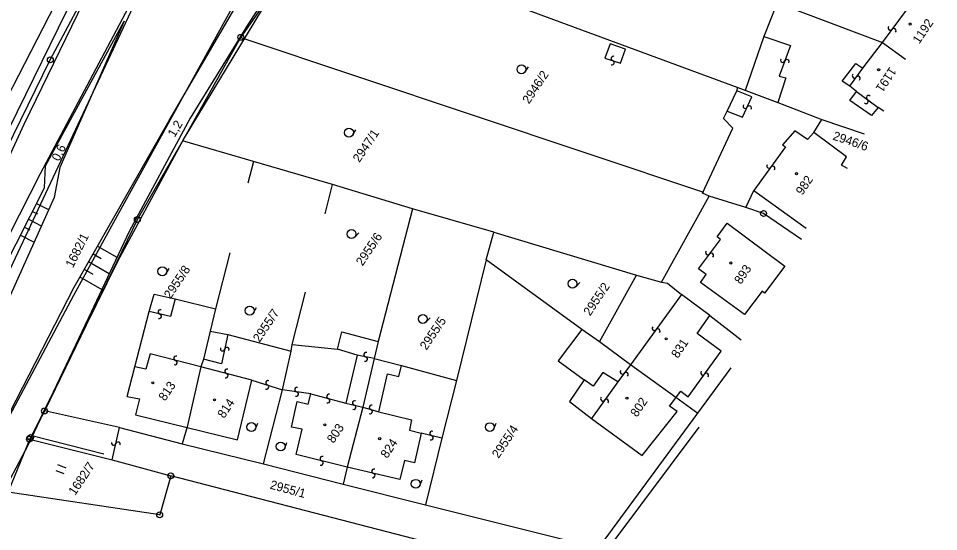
# Model space of a CAD drawing. Extents: x -658910 to -658078, y -1170373 to -1169331.
# Drawn here: x -658303.7 to -658147.9, y -1169709.4 to -1169622.6 of the extents above; entities that cross this region are included whole.
import ezdxf

# ---------------------------------------------------------------- set-up
doc = ezdxf.new("R2010")
doc.units = 0
for name, color, linetype in [('Vrstva 1', 7, 'Continuous'), ('Vrstva 10', 7, 'Continuous'), ('Vrstva 11', 7, 'Continuous'), ('Vrstva 12', 7, 'Continuous'), ('Vrstva 8', 7, 'Continuous'), ('Vrstva 9', 7, 'Continuous')]:
    doc.layers.add(name, color=color, linetype=linetype)

msp = doc.modelspace()

# ---------------------------------------------------------------- linework, layer by layer
at = {"layer": 'Vrstva 1'}
for p, q in [((-658253.461, -1169607.728), (-658266.16, -1169625.929)), ((-658266.16, -1169625.929), (-658275.871, -1169643.228)), ((-658266.1, -1169625.8), (-658266, -1169625.8)), ((-658298.339, -1169629.6), (-658298.239, -1169629.6)), ((-658275.871, -1169643.228), (-658283.521, -1169656.539)), ((-658283.521, -1169656.539), (-658299.242, -1169688.919)), ((-658283.61, -1169656.6), (-658283.51, -1169656.6)), ((-658299.242, -1169688.919), (-658301.781, -1169693.669)), ((-658299.331, -1169688.98), (-658299.231, -1169688.98)), ((-658301.87, -1169693.73), (-658301.77, -1169693.73)), ((-658301.82, -1169693.73), (-658287.82, -1169697.23)), ((-658301.672, -1169693.458), (-658301.572, -1169693.458)), ((-658301.672, -1169693.458), (-658301.572, -1169693.458)), ((-658287.82, -1169697.23), (-658277.891, -1169699.949)), ((-658277.891, -1169699.949), (-658279.77, -1169706.539)), ((-658277.941, -1169699.949), (-658277.841, -1169699.949)), ((-658279.77, -1169706.539), (-658305.441, -1169702.699)), ((-658279.82, -1169706.539), (-658279.72, -1169706.539))]:
    msp.add_line(p, q, dxfattribs=at)
msp.add_lwpolyline([(-658387.09, -1169803.74), (-658379.66, -1169787.031), (-658371.41, -1169770.08), (-658363.031, -1169753.09), (-658350.949, -1169718.6), (-658329.91, -1169685.09), (-658309.48, -1169652.309), (-658298.289, -1169629.6), (-658291.762, -1169617.34), (-658282.25, -1169598.42), (-658273.73, -1169581.691), (-658253.98, -1169552.23), (-658232.398, -1169524.699), (-658206.289, -1169500.25)], dxfattribs=at)
for centre in [(-658266.05, -1169625.8), (-658298.289, -1169629.6), (-658283.56, -1169656.6), (-658299.281, -1169688.98), (-658301.82, -1169693.73), (-658301.622, -1169693.458), (-658301.622, -1169693.458), (-658277.891, -1169699.949), (-658279.77, -1169706.539)]:
    msp.add_circle(centre, 0.499, dxfattribs=at)
at = {"layer": 'Vrstva 10'}
for points in [[(-658276.584, -1169590.485), (-658283.44, -1169602.541), (-658287.975, -1169611.492), (-658289.687, -1169613.574), (-658302.78, -1169640.536), (-658308.513, -1169652.938), (-658311.735, -1169652.624), (-658329.784, -1169644.735), (-658339.953, -1169641.872), (-658339.466, -1169639.877), (-658334.347, -1169641.667), (-658319.785, -1169646.697), (-658309.854, -1169650.681), (-658305.208, -1169641.097), (-658290.001, -1169610.092), (-658286.058, -1169602.153), (-658278.256, -1169587.533)], [(-658412.34, -1169868.25), (-658390.58, -1169825.61), (-658346.68, -1169740.23), (-658319.39, -1169686.96), (-658299.95, -1169648.82), (-658273.229, -1169598.35)], [(-658333.115, -1169751.576), (-658323.796, -1169728.025), (-658308.485, -1169695.615), (-658294.271, -1169668.043), (-658278.157, -1169639.847), (-658267.473, -1169621.543), (-658253.549, -1169598.254)], [(-658249.659, -1169600.535), (-658264.767, -1169623.458), (-658274.587, -1169639.486), (-658284.944, -1169658.621), (-658291.388, -1169672.25), (-658302.068, -1169694.842), (-658312.164, -1169713.774), (-658318.886, -1169726.345), (-658324.9, -1169737.364), (-658333.115, -1169751.576)], [(-658354.813, -1169800), (-658338.217, -1169761.133), (-658328.016, -1169737.523), (-658311.372, -1169701.327), (-658294.326, -1169669.378), (-658287.561, -1169657.031), (-658267.485, -1169620.8), (-658262.54, -1169612.307), (-658258.99, -1169605.547)], [(-658375.867, -1169800), (-658361.393, -1169773.644), (-658354.79, -1169760.67), (-658342.877, -1169737.984), (-658335.517, -1169720.03), (-658325.56, -1169701.303), (-658321.609, -1169695.48), (-658313.743, -1169679.786), (-658299.295, -1169651.229), (-658299.107, -1169647.523), (-658285.769, -1169623.061), (-658296.701, -1169647.814), (-658297.652, -1169652.866), (-658310.48, -1169681.38)], [(-658300.642, -1169653.889), (-658298.581, -1169654.932)], [(-658301.319, -1169655.228), (-658300.47, -1169655.657)], [(-658302.673, -1169657.905), (-658301.776, -1169658.359)], [(-658301.996, -1169656.566), (-658299.813, -1169657.67)], [(-658303.35, -1169659.243), (-658301.045, -1169660.409)], [(-658291.054, -1169662.414), (-658289.695, -1169663.19)], [(-658290.31, -1169661.111), (-658287.013, -1169662.996)], [(-658291.798, -1169663.716), (-658288.299, -1169665.716)], [(-658292.543, -1169665.019), (-658291.103, -1169665.841)], [(-658293.287, -1169666.321), (-658289.585, -1169668.437)]]:
    msp.add_lwpolyline(points, dxfattribs=at)
at = {"layer": 'Vrstva 11'}
for p, q in [((-658295.612, -1169698.653), (-658297.003, -1169698.092)), ((-658297.377, -1169699.019), (-658295.985, -1169699.58)), ((-658295.798, -1169699.116), (-658295.798, -1169699.116))]:
    msp.add_line(p, q, dxfattribs=at)
at = {"layer": 'Vrstva 12'}
msp.add_lwpolyline([(-658289.246, -1169696.288), (-658301.393, -1169693.156), (-658286.864, -1169663.622), (-658275.728, -1169643.056), (-658260.067, -1169617.171), (-658247.717, -1169599.265)], dxfattribs=at)
msp.add_lwpolyline([(-658289.246, -1169696.288), (-658301.393, -1169693.156), (-658286.864, -1169663.622), (-658275.728, -1169643.056), (-658260.067, -1169617.171), (-658247.717, -1169599.265)], dxfattribs=at)
at = {"layer": 'Vrstva 8'}
for p, q in [((-658203.5, -1169626.871), (-658203.5, -1169626.871)), ((-658200.93, -1169627.77), (-658200.93, -1169627.77)), ((-658204.422, -1169629.32), (-658204.422, -1169629.32)), ((-658177.601, -1169655.6), (-658177.501, -1169655.6)), ((-658301.781, -1169693.669), (-658305.402, -1169702.638)), ((-658277.941, -1169699.949), (-658277.841, -1169699.949)), ((-658208.629, -1169717.84), (-658277.891, -1169699.949))]:
    msp.add_line(p, q, dxfattribs=at)
for points in [[(-658314.059, -1169652.35), (-658295.309, -1169616), (-658286.199, -1169597.941), (-658283.891, -1169593.469), (-658276.852, -1169580.85), (-658266.91, -1169566.039), (-658264.172, -1169561.6), (-658257.539, -1169550.99), (-658245.52, -1169536.1), (-658234.621, -1169522.359), (-658224.73, -1169512.711), (-658221.309, -1169509.051), (-658215.941, -1169504.039), (-658211.672, -1169500.27)], [(-658173.84, -1169604.961), (-658176.148, -1169610.199), (-658179.391, -1169618.211), (-658175.27, -1169619.961), (-658157.449, -1169626.67), (-658151.891, -1169619.15), (-658150.531, -1169620.121), (-658149.301, -1169618.24), (-658147.93, -1169619.32)], [(-658340.286, -1169739.901), (-658283.367, -1169618.664)], [(-658224.734, -1169618.434), (-658181.91, -1169634.281)], [(-658175.27, -1169619.961), (-658177.52, -1169625.66), (-658173.02, -1169627.18), (-658174.93, -1169632.391), (-658173.789, -1169632.629), (-658175.141, -1169636.83), (-658167.672, -1169639.67), (-658160.551, -1169642.1)], [(-658266.05, -1169625.8), (-658187.749, -1169651.951)], [(-658177.52, -1169625.66), (-658180.699, -1169634.76)], [(-658157.191, -1169638.301), (-658158.172, -1169637.641), (-658159.301, -1169639.01), (-658162.941, -1169636.5), (-658161.82, -1169634.98), (-658162.98, -1169634.039), (-658164.23, -1169633.211), (-658161.949, -1169630.219), (-658160.762, -1169631.01), (-658157.449, -1169626.67), (-658153.531, -1169629.461)], [(-658162.98, -1169634.039), (-658160.762, -1169631.01)], [(-658180.578, -1169654.59), (-658186.738, -1169652.629), (-658187.898, -1169652.141), (-658182.738, -1169641.141), (-658184.32, -1169639.531), (-658183.738, -1169638.27), (-658181.102, -1169639.32), (-658179.531, -1169635.85), (-658182.109, -1169634.85), (-658181.91, -1169634.281), (-658175.141, -1169636.83)], [(-658183.738, -1169638.27), (-658182.109, -1169634.85)], [(-658161.82, -1169634.98), (-658158.172, -1169637.641)], [(-658163.352, -1169647.949), (-658164.371, -1169647.391), (-658163.5, -1169646), (-658169.07, -1169641.871), (-658167.672, -1169639.67)], [(-658169.07, -1169641.871), (-658170.109, -1169643.08), (-658172.281, -1169641.58), (-658174.371, -1169643.99), (-658173.82, -1169644.34), (-658179.199, -1169651.699), (-658170.32, -1169658.07)], [(-658223.191, -1169658.73), (-658237, -1169654.789), (-658250.52, -1169650.67), (-658263.91, -1169646.781), (-658275.91, -1169643.289)], [(-658263.91, -1169646.781), (-658264.865, -1169650.478)], [(-658251.779, -1169655.662), (-658250.52, -1169650.67)], [(-658171.141, -1169660.01), (-658177.551, -1169655.6), (-658180.578, -1169654.59), (-658179.199, -1169651.699)], [(-658194.82, -1169667.191), (-658186.738, -1169652.629)], [(-658237, -1169654.789), (-658242.77, -1169677.211), (-658243.441, -1169680.09), (-658245.391, -1169688.32), (-658248.059, -1169698.48), (-658248.73, -1169701.371)], [(-658208.328, -1169675.18), (-658224.488, -1169663.43), (-658223.191, -1169658.73), (-658199.09, -1169666)], [(-658267.898, -1169662.224), (-658270.34, -1169671.68), (-658271.219, -1169675.49), (-658272.359, -1169680.219), (-658272.789, -1169681.52), (-658275.148, -1169691.65), (-658275.941, -1169694.531)], [(-658224.488, -1169663.43), (-658229.512, -1169683.82), (-658232.012, -1169693.559), (-658234.762, -1169704.85)], [(-658205.328, -1169677.309), (-658199.09, -1169666), (-658194.82, -1169667.191), (-658193.84, -1169667.35), (-658191.422, -1169669.281)], [(-658264.16, -1169683.75), (-658272.789, -1169681.52), (-658281.398, -1169679.34), (-658282.102, -1169681.92), (-658283.961, -1169681.5), (-658281.57, -1169672.17), (-658280.711, -1169669.219), (-658277.18, -1169670.031), (-658277.941, -1169673.02), (-658281.57, -1169672.17)], [(-658277.18, -1169670.031), (-658270.34, -1169671.68)], [(-658262.211, -1169697.93), (-658258.988, -1169685.41), (-658257.52, -1169678.891), (-658257.34, -1169677.711), (-658255.116, -1169668.895)], [(-658188.68, -1169689.42), (-658192.391, -1169686.711), (-658200.078, -1169681.17), (-658205.328, -1169677.309), (-658208.328, -1169675.18), (-658212.34, -1169680.5), (-658207.922, -1169683.691), (-658210.43, -1169687.4), (-658206.699, -1169690.26), (-658198.078, -1169696.51), (-658192.199, -1169689.051), (-658193.461, -1169688.17), (-658191.539, -1169685.621), (-658190.328, -1169686.609), (-658184.73, -1169678.879), (-658188.789, -1169675.859), (-658186.66, -1169672.84), (-658191.422, -1169669.281), (-658200.078, -1169681.17), (-658202.219, -1169684.039), (-658204.762, -1169682.48), (-658206.398, -1169684.801), (-658207.922, -1169683.691)], [(-658186.66, -1169672.84), (-658181.34, -1169676.949)], [(-658271.219, -1169675.49), (-658268.23, -1169676.051), (-658269.301, -1169680.98), (-658272.359, -1169680.219)], [(-658268.23, -1169676.051), (-658257.52, -1169678.891)], [(-658257.34, -1169677.711), (-658249.672, -1169678.531), (-658248.949, -1169675.6), (-658242.77, -1169677.211)], [(-658243.441, -1169680.09), (-658246.371, -1169679.57), (-658249.672, -1169678.531)], [(-658246.371, -1169679.57), (-658248.289, -1169687.65), (-658245.391, -1169688.32), (-658242.68, -1169689.109), (-658241.211, -1169682.691), (-658239.289, -1169683.16), (-658238.82, -1169681.301), (-658229.512, -1169683.82)], [(-658243.441, -1169680.09), (-658238.82, -1169681.301)], [(-658285.281, -1169686.551), (-658283.961, -1169681.5)], [(-658183.09, -1169681.691), (-658204.57, -1169710.879), (-658203.199, -1169711.379), (-658188.441, -1169691.711)], [(-658285.281, -1169686.551), (-658283.211, -1169686.949), (-658283.852, -1169689.629), (-658266.629, -1169693.84), (-658264.16, -1169683.75), (-658258.988, -1169685.41)], [(-658202.219, -1169684.039), (-658206.699, -1169690.26)], [(-658232.012, -1169693.559), (-658235.539, -1169692.74), (-658236.648, -1169697.73), (-658238.309, -1169697.34), (-658239.141, -1169700.58), (-658248.059, -1169698.48), (-658256.672, -1169696.35), (-658255.68, -1169692.08), (-658257.488, -1169691.699), (-658256.512, -1169687.379), (-658254.648, -1169687.809), (-658254.211, -1169686.109), (-658258.988, -1169685.41)], [(-658254.211, -1169686.109), (-658248.289, -1169687.65)], [(-658286.551, -1169691.789), (-658299.281, -1169688.98)], [(-658242.68, -1169689.109), (-658237.129, -1169690.49), (-658237.512, -1169692.23), (-658235.539, -1169692.74)], [(-658287.82, -1169697.23), (-658286.551, -1169691.789), (-658275.941, -1169694.531), (-658262.211, -1169697.93), (-658248.73, -1169701.371), (-658234.762, -1169704.85), (-658206.59, -1169711.91), (-658204.57, -1169710.879), (-658208.629, -1169717.84)]]:
    msp.add_lwpolyline(points, dxfattribs=at)
for points in [[(-658201.789, -1169630.16), (-658200.93, -1169627.77), (-658203.5, -1169626.871), (-658204.422, -1169629.32)], [(-658183.691, -1169657.219), (-658173.949, -1169664.469), (-658177.379, -1169669.07), (-658177.82, -1169668.711), (-658180.762, -1169672.67), (-658188.238, -1169667.26), (-658187.262, -1169665.91), (-658188.57, -1169664.93), (-658184.828, -1169659.99), (-658185.43, -1169659.551)]]:
    msp.add_lwpolyline(points, close=True, dxfattribs=at)
for centre in [(-658177.551, -1169655.6), (-658277.891, -1169699.949)]:
    msp.add_circle(centre, 0.499, dxfattribs=at)
for centre, radius, start, end in [((-658156.11, -1169624.204), 0.376, 136.7959, 323.10703), ((-658155.505, -1169624.652), 0.377, 316.11986, 143.78307), ((-658203.216, -1169630.098), 0.377, 244.63753, 72.30074), ((-658202.983, -1169629.382), 0.376, 65.31357, 251.6247), ((-658174.321, -1169629.655), 0.376, 152.96811, 339.27924), ((-658173.615, -1169629.918), 0.377, 332.29207, 159.95528), ((-658162.171, -1169632.304), 0.376, 136.76212, 323.07326), ((-658161.567, -1169632.753), 0.377, 316.08608, 143.74929), ((-658159.778, -1169636.004), 0.377, 46.31615, 233.97936), ((-658180.66, -1169637.43), 0.376, 148.60841, 334.91955), ((-658179.977, -1169637.745), 0.377, 327.93237, 155.59559), ((-658160.224, -1169636.61), 0.376, 226.99219, 53.30333), ((-658176.636, -1169647.566), 0.376, 140.91027, 327.2214), ((-658176, -1169647.97), 0.377, 320.23423, 147.89744), ((-658186.996, -1169662.23), 0.376, 135.8428, 322.15393), ((-658186.398, -1169662.688), 0.377, 315.16676, 142.82997), ((-658279.671, -1169672.234), 0.376, 69.7521, 256.06323), ((-658279.848, -1169672.966), 0.377, 249.07606, 76.73927), ((-658196.051, -1169674.993), 0.376, 136.97729, 323.28842), ((-658195.445, -1169675.44), 0.377, 316.30124, 143.96446), ((-658276.993, -1169680.066), 0.376, 68.82322, 255.13436), ((-658269.136, -1169678.436), 0.376, 160.81958, 347.13071), ((-658268.401, -1169678.599), 0.377, 340.14354, 167.80675), ((-658244.839, -1169679.46), 0.376, 72.95052, 259.26166), ((-658277.182, -1169680.795), 0.377, 248.14718, 75.81039), ((-658244.975, -1169680.2), 0.377, 252.27448, 79.93769), ((-658268.381, -1169682.277), 0.376, 68.52471, 254.83584), ((-658268.574, -1169683.005), 0.377, 247.84867, 75.51188), ((-658201.447, -1169682.38), 0.376, 136.32295, 322.63408), ((-658200.846, -1169682.834), 0.377, 315.64691, 143.31012), ((-658187.833, -1169682.525), 0.376, 137.13392, 323.44505), ((-658187.225, -1169682.97), 0.377, 316.45788, 144.12109), ((-658261.458, -1169684.222), 0.376, 65.22699, 251.53813), ((-658261.693, -1169684.938), 0.377, 244.55095, 72.21417), ((-658256.543, -1169685.388), 0.376, 74.77253, 261.08366), ((-658256.656, -1169686.132), 0.377, 254.09649, 81.7597), ((-658251.151, -1169686.515), 0.376, 68.46186, 254.77299), ((-658251.344, -1169687.243), 0.377, 247.78582, 75.44903), ((-658246.75, -1169687.614), 0.376, 69.94284, 256.25397), ((-658204.763, -1169686.926), 0.376, 137.23292, 323.54406), ((-658204.155, -1169687.37), 0.377, 316.55688, 144.22009), ((-658246.925, -1169688.346), 0.377, 249.2668, 76.93001), ((-658243.929, -1169688.358), 0.376, 66.72579, 253.03693), ((-658244.144, -1169689.08), 0.377, 246.04975, 73.71297), ((-658233.68, -1169692.784), 0.376, 69.98478, 256.29591), ((-658233.855, -1169693.516), 0.377, 249.30874, 76.97195), ((-658287.556, -1169694.419), 0.376, 159.85414, 346.16528), ((-658286.824, -1169694.595), 0.377, 339.1781, 166.84132), ((-658252.268, -1169697.044), 0.377, 68.4467, 256.10992), ((-658252.453, -1169697.774), 0.376, 249.12274, 75.43388), ((-658243.515, -1169699.164), 0.377, 69.08876, 256.75197), ((-658243.692, -1169699.896), 0.376, 249.7648, 76.07593)]:
    msp.add_arc(centre, radius, start, end, dxfattribs=at)
at = {"layer": 'Vrstva 9'}
for p, q in [((-658217.916, -1169631.631), (-658217.354, -1169630.805)), ((-658247.084, -1169642.287), (-658246.595, -1169641.415)), ((-658246.755, -1169659.572), (-658246.068, -1169658.847)), ((-658278.665, -1169665.739), (-658278.176, -1169664.867)), ((-658209.357, -1169667.96), (-658208.67, -1169667.235)), ((-658263.887, -1169672.38), (-658263.398, -1169671.508)), ((-658234.685, -1169673.929), (-658233.998, -1169673.204)), ((-658263.552, -1169691.98), (-658263.179, -1169691.053)), ((-658223.196, -1169691.988), (-658222.823, -1169691.061)), ((-658258.605, -1169695.265), (-658258.232, -1169694.338)), ((-658235.736, -1169701.575), (-658235.363, -1169700.648))]:
    msp.add_line(p, q, dxfattribs=at)
for centre, radius in [((-658152.753, -1169623.55), 0.175), ((-658218.537, -1169631.21), 0.75), ((-658158.079, -1169631.274), 0.175), ((-658247.739, -1169641.921), 0.75), ((-658171.965, -1169648.846), 0.175), ((-658247.3, -1169659.057), 0.75), ((-658183.083, -1169663.957), 0.175), ((-658279.32, -1169665.373), 0.75), ((-658209.902, -1169667.445), 0.75), ((-658264.542, -1169672.014), 0.75), ((-658235.23, -1169673.414), 0.75), ((-658194.046, -1169676.785), 0.175), ((-658280.948, -1169684.205), 0.175), ((-658270.509, -1169687.098), 0.175), ((-658200.679, -1169686.803), 0.175), ((-658264.248, -1169691.7), 0.75), ((-658251.83, -1169691.331), 0.175), ((-658223.892, -1169691.708), 0.75), ((-658242.537, -1169693.657), 0.175), ((-658259.301, -1169694.985), 0.75), ((-658236.432, -1169701.295), 0.75)]:
    msp.add_circle(centre, radius, dxfattribs=at)

# ---------------------------------------------------------------- texts
at = {"layer": 'Vrstva 11'}
for s, rotation, p in [('1,2', 59.39166, (-658277.237, -1169642.808)), ('0,6', 63.71784, (-658296.806, -1169646.867)), ('1682/1', 63.34135, (-658294.463, -1169664.882)), ('1682/7', 56.1528, (-658294.094, -1169703.368))]:
    msp.add_text(s, height=1.5, rotation=rotation, dxfattribs=at).set_placement(p)
at = {"layer": 'Vrstva 9'}
for s, rotation, p in [('1192', 56.1528, (-658151.217, -1169627.02)), ('2946/2', 56.1528, (-658217.266, -1169637.166)), ('1191', 236.1528, (-658156.177, -1169630.69)), ('2947/1', 56.1528, (-658245.972, -1169647.068)), ('2946/6', 341.21691, (-658165.961, -1169643.059)), ('982', 56.1528, (-658170.986, -1169652.589)), ('2955/6', 56.1528, (-658245.431, -1169664.564)), ('2955/8', 56.1528, (-658277.935, -1169670.12)), ('893', 56.1528, (-658181.394, -1169667.665)), ('2955/2', 56.1528, (-658206.921, -1169673.006)), ('2955/7', 56.1528, (-658262.864, -1169677.471)), ('2955/5', 56.1528, (-658234.612, -1169678.794)), ('831', 56.1528, (-658192.066, -1169680.179)), ('813', 56.1528, (-658278.85, -1169687.41)), ('814', 56.1528, (-658268.875, -1169690.329)), ('802', 56.1528, (-658198.983, -1169690.125)), ('803', 56.1528, (-658250.343, -1169694.542)), ('2955/4', 56.1528, (-658222.411, -1169697.1)), ('824', 56.1528, (-658241.268, -1169697.099)), ('2955/1', 344.69919, (-658261.211, -1169702.09))]:
    msp.add_text(s, height=1.5, rotation=rotation, dxfattribs=at).set_placement(p)

doc.saveas('drawing.dxf')
